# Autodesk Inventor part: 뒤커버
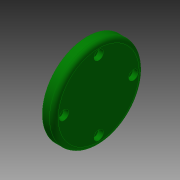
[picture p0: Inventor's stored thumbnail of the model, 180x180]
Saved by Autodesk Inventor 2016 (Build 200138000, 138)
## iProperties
Created: 2015-09
Part Number: 뒤커버
Material: 알루미늄 6061
Document SubType Name: Modeling
Designer: mduedu
Density: 2.71 g/cm^3
Mass: 54.0417 g
Surface Area: 84.9688 cm^2
Volume: 19.9416 cm^3
Appearance: 진녹색
Author: mduedu
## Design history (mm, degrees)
sketch "스케치1"
  geometry: L1 (-15.5, 47)-(-15.5, 78); L2 (-15.5, 78)-(-23.5, 78); L3 (-23.5, 78)-(-23.5, 67); L4 (-27.5, 67)-(-27.5, 47); L5 (-79.5, 39.5)-(-79.5, 54.5) reference; L6 (48.5, 54.5)-(48.5, 39.5) reference; L7 (-79.5, 47)-(48.5, 47); L8 (-23.5, 67)-(-27.5, 67); L9 (-27.5, 47)-(-15.5, 47); 1 further point
  constraints: 14 end point, 4 midpoint, 3 parallel, 1 collinear, 1 point on line, 1 vertical
  dimensions: "d6" = 62 diameter of L2 L7; "d7" = 8 distance of L1.end L2.end; "d8" = 40 diameter of L3.end L7; "d32" = 12 distance between parallel lines of L1 L4
revolve "회전1" sketch "스케치1" stored, may be unused: angle "d4" = 90 deg
sketch "스케치4"
  geometry: C1 r 31 at (0, 0) reference; 2 further points
  constraints: 1 coincident
hole "구멍3" sketch "스케치4" at (0, 0) diameter "d33" = 33; stored, may be unused: countersink angle "d37" = 90 deg, drill point angle "d39" = 0 deg; dims "d34" = 6, "d35" = 4, "d36" = 2, "d38" = 5
fillet "모깎기4" dims "d56" = 3
chamfer "모따기2" distance "d41" = 1; stored, may be unused: second distance "d42" = 2, angle "d43" = 45 deg
sketch "스케치5" dims "d44" = 48
  geometry: C1 r 31 at (0, 0) reference; 6 further points
  constraints: 2 vertical alignment, 1 coincident, 7 other
  dimensions: "d47" = 360 deg dimension on C1.centre point (0, -24) (derived)
sketch "스케치6"
  geometry: C1 r 28 at (0, 0) reference; A1 r 24 centre (0, 0) between (24, 0) and (0, 24); 2 further points
  constraints: 4 point on circle, 2 horizontal alignment, 2 vertical alignment, 1 centre point, 1 coincident
  dimensions: "d57" = 48 diameter of A1
hole "구멍4" sketch "스케치6" at (24, 0), (0, 24), (-24, 0), (0, -24) diameter "d49" = 3.4; stored, may be unused: countersink angle "d53" = 90 deg, drill point angle "d55" = 0 deg; dims "d50" = 6, "d51" = 6.5, "d52" = 3.4, "d54" = 8
node "솔리드1"
node "참조1"
node "참조2"
